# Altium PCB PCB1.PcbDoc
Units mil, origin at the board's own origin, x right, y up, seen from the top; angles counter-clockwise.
Board outline 6000 x 4000 mil, 2 copper layers (Top Layer, Bottom Layer); 7 components, 7 nets, 21 pads, 0 vias.
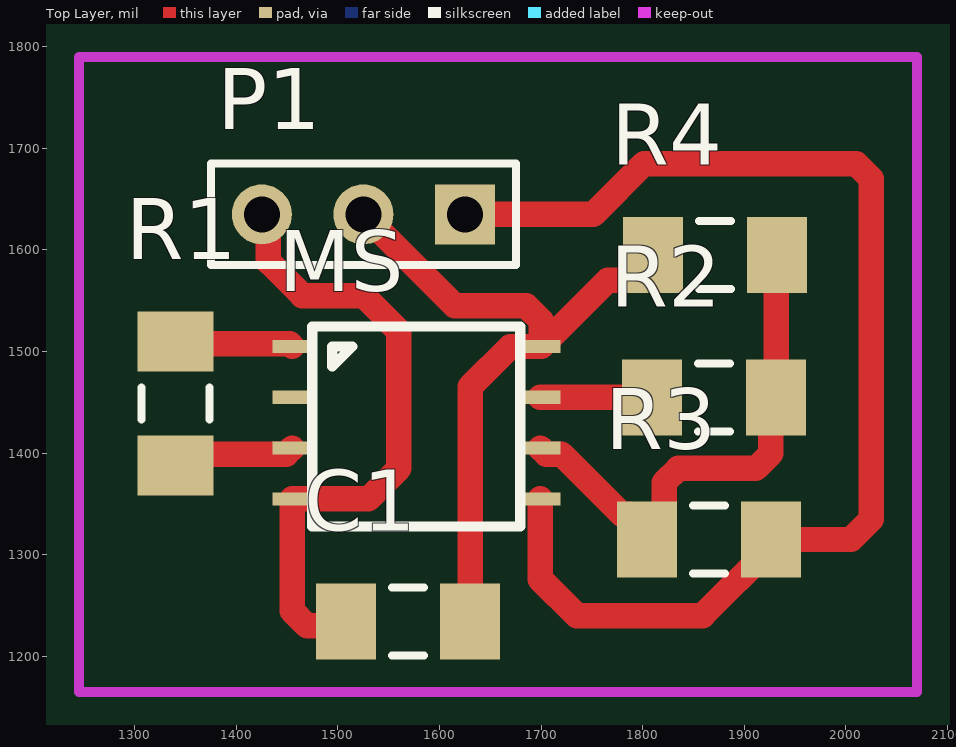
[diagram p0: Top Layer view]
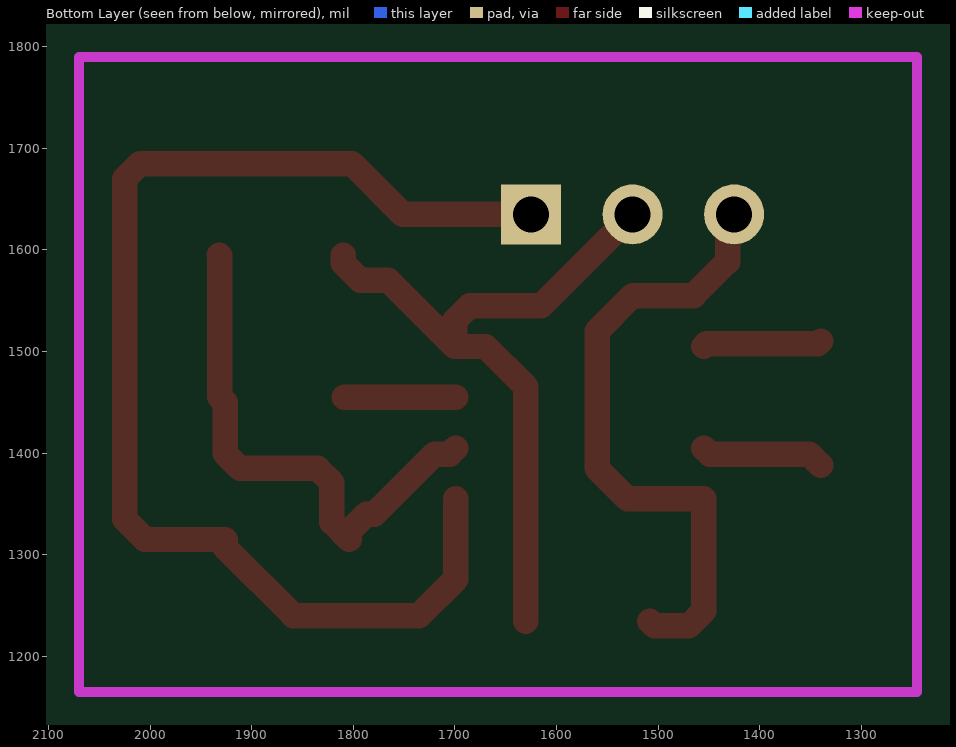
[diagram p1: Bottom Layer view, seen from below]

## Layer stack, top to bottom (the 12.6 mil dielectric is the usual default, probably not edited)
Top Solder: solder mask 0.4, Solder Resist, Dk 3.5
Top Layer: signal copper 1.4
Dielectric 1: dielectric 12.6, FR-4, Dk 4.8
Bottom Layer: signal copper 1.4
Bottom Solder: solder mask 0.4, Solder Resist, Dk 3.5

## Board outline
1000,1000 7000,1000 7000,5000 1000,5000

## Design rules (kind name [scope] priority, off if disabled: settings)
Clearance [All] p1: gap=10 ignorepadtopadclearanceinfootprint=FALSE except(0: Arc-Hole Track-Hole SMDPad-Hole THPad-Hole Via-Hole Fill-Hole Poly-Hole Region-Hole Text-Hole)
PolygonConnect [All] p1: connectstyle=Relief reliefconductorwidth=10 reliefentries=4 polygonreliefangle="90 Angle" airgapwidth=10
RoutingVias [All] p1: holewidth=28 width=50 viastyle="Through Hole" minholewidth=28 minwidth=50 maxholewidth=28 maxwidth=50
SolderMaskExpansion [All] p1: expansion=4
Width [All] p1: maxlimit=26 minlimit=25 preferedwidth=25 minimp=50.000000 maximp=50.000000 favimp=50.000000
30 further rules are at their usual default settings.

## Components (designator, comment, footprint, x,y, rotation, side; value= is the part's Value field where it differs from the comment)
C1 "Cap" CAPC3216M 1568.98,1234.53 r0 top value=0.1muF
MS "MagnetSensor" AD22151 1455,1505 r0 top
P1 "Header 3" HDR1X3 1625,1635 r180 top (schematic designator P?)
R1 "Res3" RESC3216M 1340,1448.98 r90 top value=4.7K
R2 "Res3" RESC3216M 1870,1455 r0 top value=4.7K
R3 "Res3" RESC3216M 1865,1315 r0 top value=4.7K
R4 "Res3" RESC3216M 1871.02,1595 r0 top value=4.7K

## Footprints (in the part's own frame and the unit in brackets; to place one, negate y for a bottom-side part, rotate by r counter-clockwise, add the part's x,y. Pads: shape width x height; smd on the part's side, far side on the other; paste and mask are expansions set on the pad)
AD22151 [mm] "Magnetic Sensor"
  rect 1x0.33 smd: 1(0,0) 2(0,-1.27) 3(0,-2.54) 4(0,-3.81) 5(6.2,-3.81) 6(6.2,-2.54) 7(6.2,-1.27) 8(6.2,0)
  silkscreen extent 0.5,-4.5 5.7,0.5
CAPC3216M [mm] "Chip Capacitor, Body 3.2x1.6mm, IPC Low Density"
  rect 1.5x1.9 smd: 1(-1.55,0) 2(1.55,0)
  silkscreen extent -0.4,-0.85 0.4,0.85, body extent -1.7,-0.9 1.7,0.9, height 1.35
HDR1X3 [mm] "Connector; Header; 3 Position"
  rect 1.5x1.5 hole 0.9: 1(0,0)
  round 1.5 hole 0.9: 2(2.54,0) 3(5.08,0)
  silkscreen extent -1.27,-1.27 6.35,1.27
RESC3216M [mm] "Chip Resistor, Body 3.2x1.6mm, IPC Low Density"
  rect 1.5x1.9 smd: 1(-1.55,0) 2(1.55,0)
  silkscreen extent -0.4,-0.85 0.4,0.85, body extent -1.68,-0.87 1.68,0.87, height 0.71

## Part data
C1: "Capacitor"
MS: library part Component_1
P1: "Header, 3-Pin"
R1 R2 R3 R4: "Resistor"

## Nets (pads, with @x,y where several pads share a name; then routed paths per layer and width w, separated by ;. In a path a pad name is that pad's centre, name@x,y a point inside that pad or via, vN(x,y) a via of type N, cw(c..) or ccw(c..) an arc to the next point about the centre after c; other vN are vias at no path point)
NetC1_1: C1.1 MS.4 P1.3 | length 629.7
  Top Layer w25: P1.3 1431.52,1628.48 1431.52,1588.48 1465,1555 1525,1555 1560,1520 1560,1385 1530,1355 MS.4 1455,1244.64 1469.64,1230 1503.43,1230 C1.1
NetC1_2: C1.2 MS.8 P1.2 R4.1 | length 714.5
  Top Layer w10: C1.2 C1.2@1630.91,1235.43
  Top Layer w25: P1.2 1615,1545 1685.36,1545 1700,1530.36 1700,1505.91 MS.8 ; C1.2 1630,1465.36 1669.64,1505 MS.8 ; R4.1 1810,1587.13 1792.97,1570.1 1765.37,1570.1 1700.28,1505 MS.8
NetMS_1: MS.1 R1.2 | length 117.1
  Top Layer w25: R1.2 1342.5,1507.5 1452.5,1507.5 MS.1
NetMS_3: MS.3 R1.1 | length 122.1
  Top Layer w25: R1.1 1351.04,1399 1449,1399 MS.3
NetMS_5: MS.5 P1.1 R3.2 | length 1225.8
  Top Layer w25: P1.1 1751.25,1635 1801.25,1685 2010,1685 2025,1670 2025,1335 2005,1315 R3.2 1926.02,1307.13 1858.9,1240 1735,1240 1699.09,1275.91 MS.5
NetMS_6: MS.6 R2.2 R3.1 R4.2 | length 524.6
  Top Layer w25: MS.6 1705.1,1399 1719.98,1399 1779.07,1339.9 1786.95,1339.9 1803.98,1322.87 R3.1 1821,1332.03 1821,1371 1835,1385 1911.38,1385 1926.02,1399.64 1926.02,1450 R2.2 1931.54,1455.51 1931.54,1594.49 R4.2
NetMS_7: MS.7 R2.1 | length 109.9
  Top Layer w25: MS.7 R2.1
pads on no net: MS.2

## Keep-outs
Keep-Out Layer:
  lines w10: 1250,1790 1245,1790 ; 1245,1790 2070,1790 2070,1165 1245,1165 1245,1790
